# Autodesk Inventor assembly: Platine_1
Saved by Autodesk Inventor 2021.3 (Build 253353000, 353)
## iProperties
Created: 2023-03
Part Number: Platine_1
Document SubType Name: Assembly
Designer: AdminForWorker
Title: Platine_1 v1
Author: AdminForWorker
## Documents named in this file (3)
- z:\worker\convert-fusion-r08-cosv3\tmp\job-1\3553\output\files\82b4d9ad-b575-4129-b9ca-4964d6b72adf\Platine_1 v1.iam
- z:\worker\convert-fusion-r08-cosv3\tmp\job-1\3553\output\files\82b4d9ad-b575-4129-b9ca-4964d6b72adf\Board.ipt
- z:\worker\convert-fusion-r08-cosv3\tmp\job-1\3553\output\files\82b4d9ad-b575-4129-b9ca-4964d6b72adf\Packages.ipt
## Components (2 placed, 2 different names)
1. Board:1
2. Packages:1
